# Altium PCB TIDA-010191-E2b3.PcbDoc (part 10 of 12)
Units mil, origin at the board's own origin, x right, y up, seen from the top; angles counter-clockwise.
Board outline 9842.52 x 9842.4 mil, 6 copper layers (Layer 1 - Top Layer, Layer 2 - GND Layer, Layer 3 - Signal, Layer 4 - Signal, Layer 5 - GND, Bottom Layer), stack 59.9 mil thick; 1178 components, 642 nets, 3329 pads, 2967 vias.
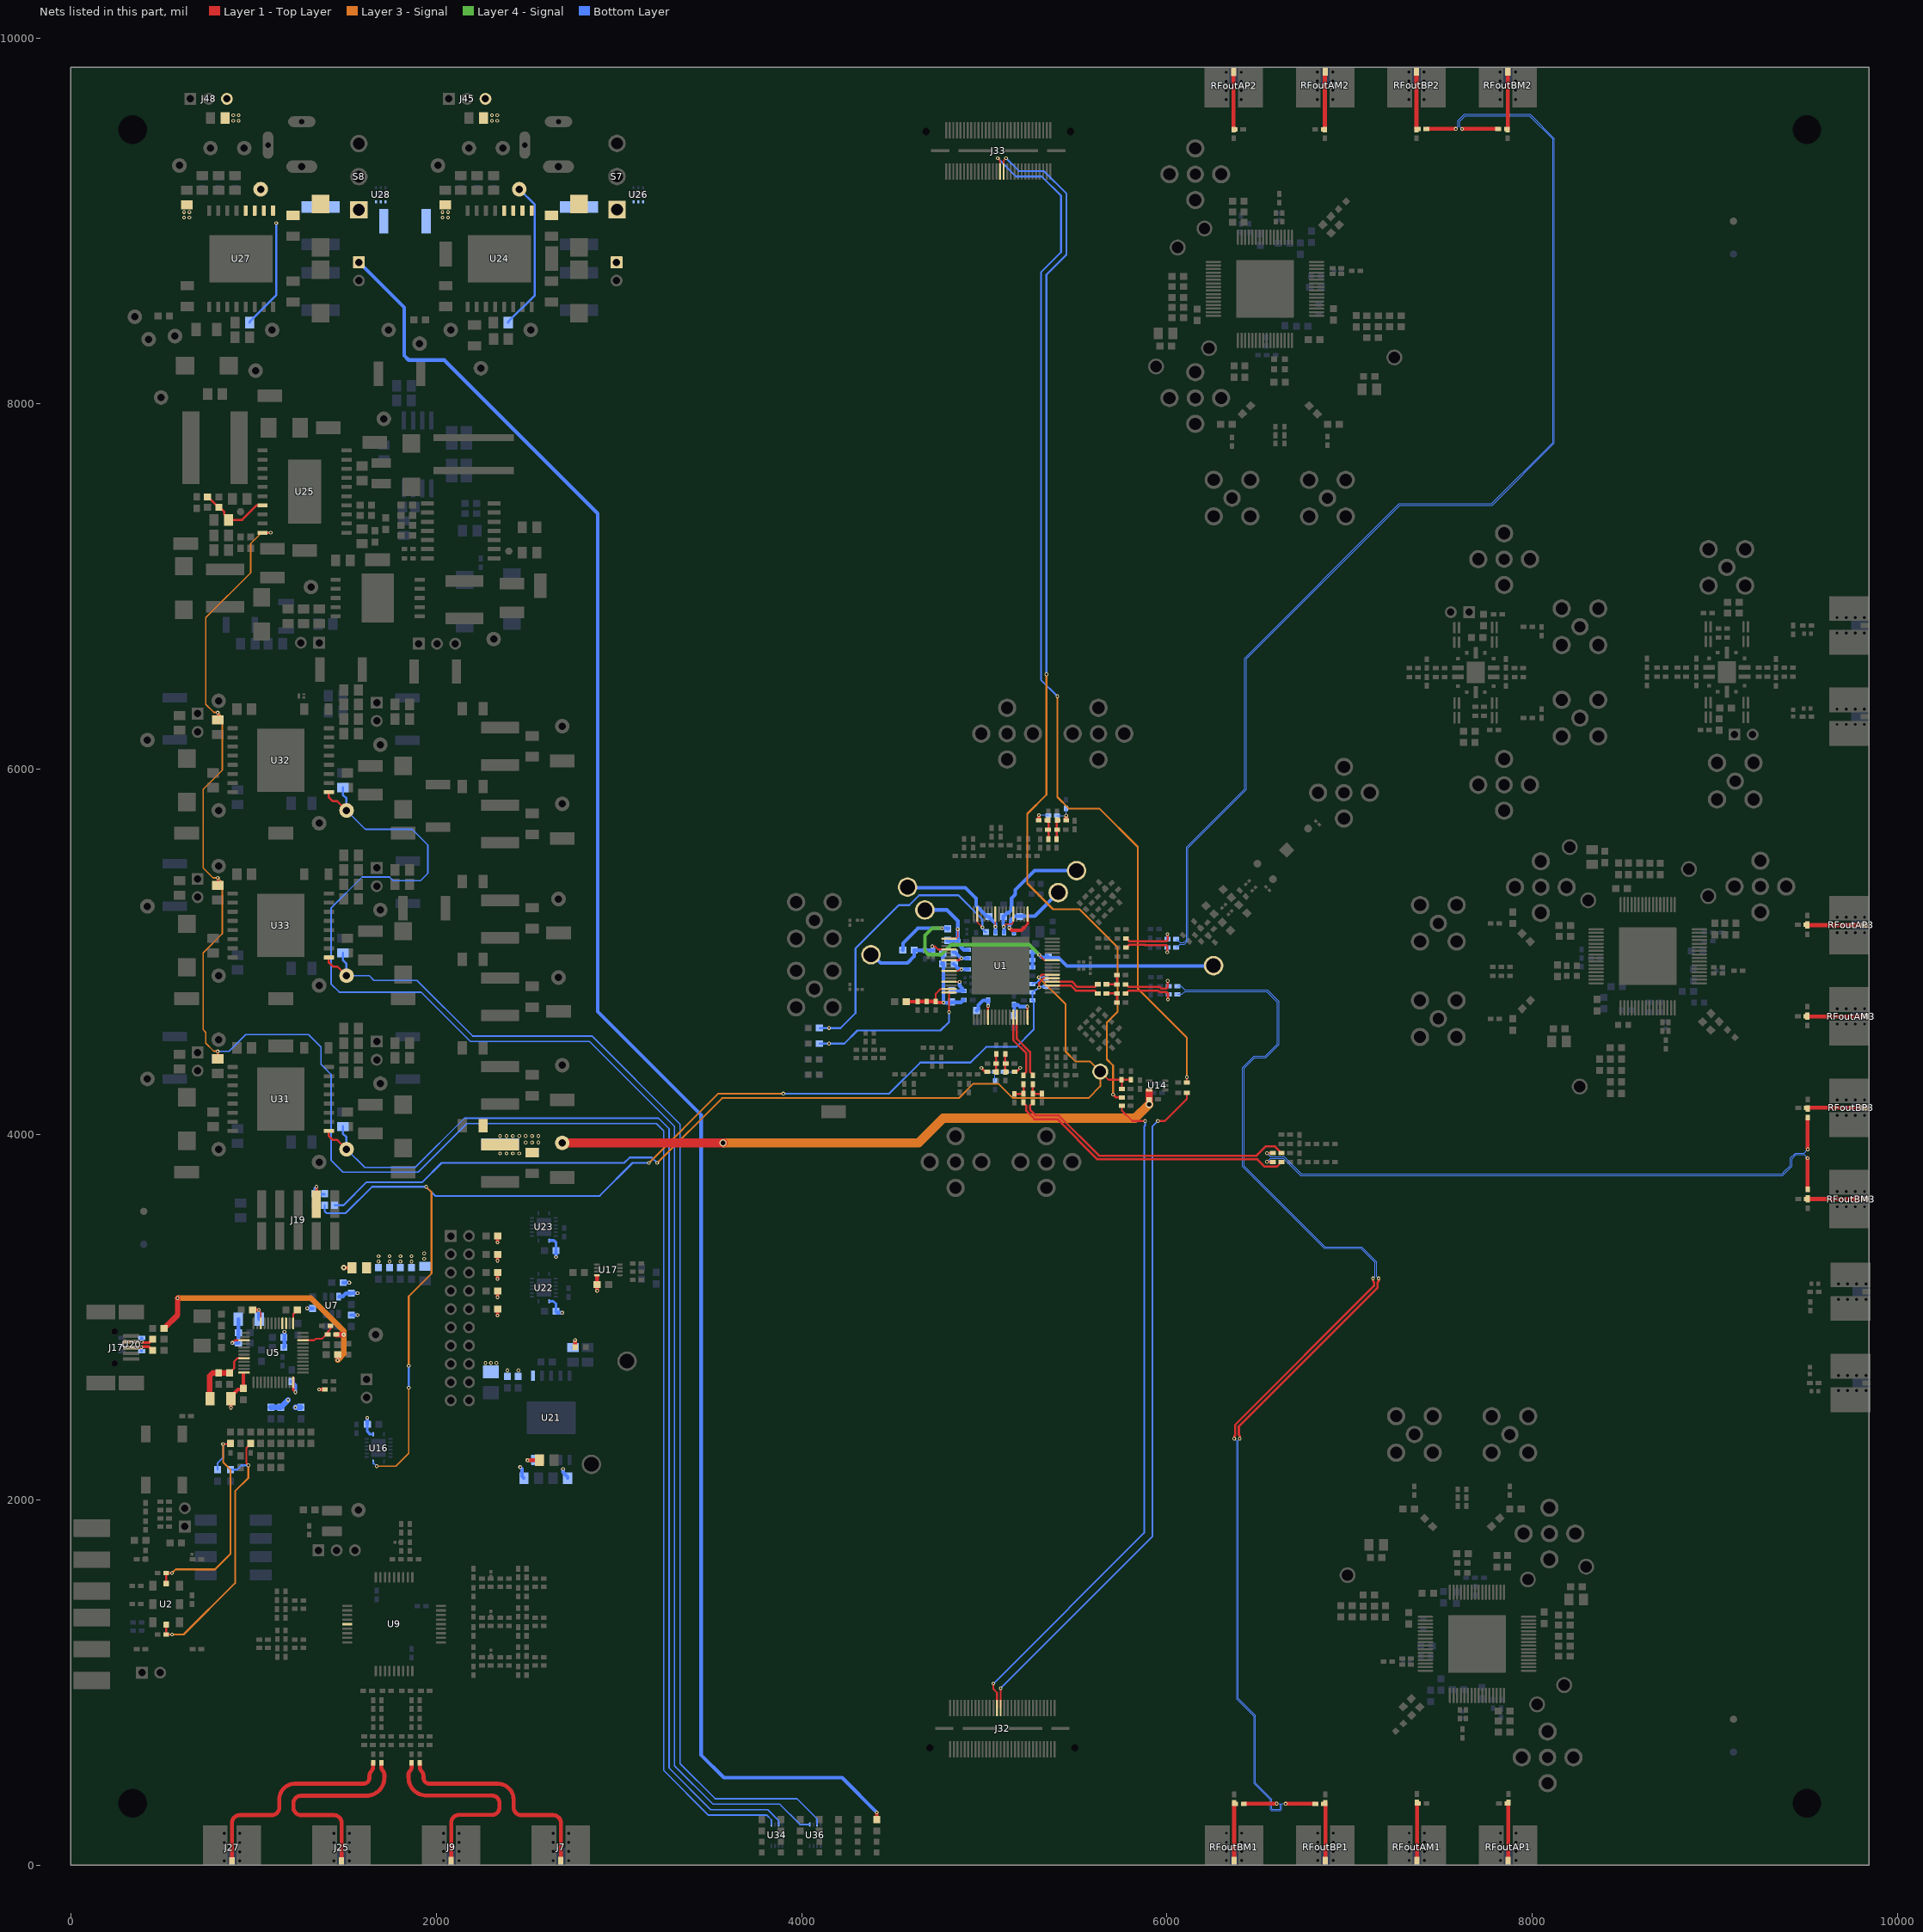
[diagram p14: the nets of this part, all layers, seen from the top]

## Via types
v1: diameter 20, hole 10, Layer 1 - Top Layer to Bottom Layer, tented both sides, 2595 vias
v2: diameter 19.68, hole 7.87, Layer 1 - Top Layer to Bottom Layer, 308 vias
v3: diameter 19.68, hole 7.87, Layer 1 - Top Layer to Bottom Layer, tented both sides, 25 vias
v4: diameter 20, hole 10, Layer 1 - Top Layer to Bottom Layer, 21 vias
v5: diameter 41, hole 25, Layer 1 - Top Layer to Bottom Layer, 10 vias
v6: diameter 24, hole 12, Layer 1 - Top Layer to Bottom Layer, tented both sides, 4 vias
v7: diameter 24, hole 8, Layer 1 - Top Layer to Bottom Layer, tented both sides, 1 vias
v8: diameter 24/24/24/24/24/24 (per signal layer), hole 8, Layer 1 - Top Layer to Bottom Layer, tented both sides, 1 vias
v9: diameter 30, hole 12, Layer 1 - Top Layer to Bottom Layer, tented both sides, 1 vias
v10: diameter 20/20/20/20/20/20 (per signal layer), hole 10, Layer 1 - Top Layer to Bottom Layer, tented both sides, 1 vias

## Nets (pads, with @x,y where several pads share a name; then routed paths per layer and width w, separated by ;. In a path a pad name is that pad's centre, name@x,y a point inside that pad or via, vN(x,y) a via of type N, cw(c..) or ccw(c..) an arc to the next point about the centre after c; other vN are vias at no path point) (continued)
PWRGD: R506.1 R508.1 R519.1 R532.1 U25.20 U34.1 | length 10936.8
  Layer 1 - Top Layer w12: R508.1@805,4415 v1(805,4455.47) ; R532.1@805,5365 v1(805,5405.47) ; R519.1@805,6269.53 v1(805,6310) ; U25.20@1050.08,7295 v1(1095,7295)
  Layer 3 - Signal w8: v1(805,4455.47) 803.47,4457 783,4457 740,4500 740,4560 725,4575 725,4995 830,5100 830,5380.47 v1(805,5405.47) 779.53,5405.47 725,5460 725,5890 830,5995 830,6285 v1(805,6310) 803,6312 783,6312 740,6355 740,6830 985,7075 985,7235 1045,7295 v1(1095,7295)
  Bottom Layer w8: R506.1@805,4415 v1(805,4455.47) 865.8,4455.47 957.47,4547.14 1302.56,4547.14 1370,4479.7 1370,4385 1425,4330 1425,3860 1490,3795 1902.43,3795 2167.43,4060 3205,4060 3245,4020 3245,520 3490,275 3810,275 3835.47,249.53 U34.1@3835.47,224.06
PWRGD_LDO_A: R507.2 TP42.1 U31.9 U34.3 | length 6470.1
  Layer 1 - Top Layer w12: U31.9@1413.5,4020 1413.5,3991.97 1435,3970.47 1459.53,3970.47 TP42.1@1510,3920
  Bottom Layer w8: TP42.1@1510,3920 1610,3820 1885,3820 2155,4090 3217.43,4090 3275,4032.43 3275,532.43 3502.43,305 3815,305 3874.49,245.51 3874.49,224.41 U34.3@3874.84,224.06
  Bottom Layer w12: R507.2@1490,4045.47 R507.2@1490,4045 1490,4005.47 1510,3985.47 TP42.1@1510,3920
PWRGD_LDO_B: R518.2 TP55.1 U32.9 U36.1 | length 8583.5
  Layer 1 - Top Layer w12: U32.9@1413.5,5874.53 1413.5,5846.5 1435,5825 1459.53,5825 TP55.1@1510,5774.53
  Bottom Layer w8: TP55.1@1510,5774.53 1612.95,5671.57 1868.43,5671.57 1955,5585 1955,5430 1915,5390 1765,5390 1745,5410 1595,5410 1425,5240 1425,4825 1470,4780 1917.57,4780 2187.57,4510 2840,4510 3305,4045 3305,544.85 3514.85,335 3880,335 3990.94,224.06 U36.1@4045.47,224.06
  Bottom Layer w12: R518.2@1490,5900 1490,5860 1510,5840 TP55.1@1510,5774.53
PWRGD_LDO_C: R531.2 TP68.1 U33.9 U36.3 | length 6855.9
  Layer 1 - Top Layer w12: U33.9@1413.5,4970 1413.5,4941.97 1435,4920.47 1459.53,4920.47 TP68.1@1510,4870
  Bottom Layer w8: TP68.1@1510,4870 1635,4870 1660,4845 1895,4845 2200,4540 2852.43,4540 3335,4057.43 3335,557.28 3527.28,365 3975,365 4084.84,255.16 U36.3@4084.84,224.06
  Bottom Layer w12: R531.2@1490,4995.47 R531.2@1490,4995 1490,4955.47 1510,4935.47 TP68.1@1510,4870
R_ELMK_SDO: J19.3 R305.2 R311.2 | length 195
  Layer 1 - Top Layer w13.5: J19.3@1345,3620.06 v1(1345,3715)
  Bottom Layer w13.5: v1(1345,3715) 1335,3705 R305.2@1335,3676.5 1335,3674.06 R311.2@1390,3674.06
RESET: C184.1 R35.2 R311.1 R343.1 U1.5 U16.9 | length 6542.5
  Layer 1 - Top Layer w10: v1(5300,4805) 5300,4829.71 5300.13,4829.84 ; 5300.05,4830.05 5326.1,4856.1 U1.5@5372.48,4856.1
  Layer 3 - Signal w8: v1(1675,2185) 1780,2185 1850,2255 v1(1850,2615)
  Layer 3 - Signal w10: v1(1850,2735) 1850,3115 1975,3240 1975,3685 v1(1945,3715) ; v1(3165,3845) 3545,4225 v1(3900,4225)
  Bottom Layer w8: U16.9@1655.47,2210.2 1655.47,2204.53 v1(1675,2185)
  Bottom Layer w10: R311.1@1390,3613.5 1390,3580 1400,3570 1505,3570 1650,3715 v1(1945,3715) 1995,3665 2895,3665 3075,3845 v1(3165,3845) ; v1(1850,2615) v1(1850,2735) ; v1(3900,4225) 4480.33,4225 4650.33,4395 4925,4395 5010,4480 5175,4480 5270,4575 5270,4730 5265,4735 R35.2@5263.62,4735 ; R35.2@5259.68,4735 R35.2@5263.62,4735 ; R343.1@5336.38,4810 5305,4810 v1(5300,4805) 5297.29,4805 5286.23,4793.93 5281.49,4793.93 5267.56,4780 C184.1@5263.62,4780 5263.62,4775 R35.2@5263.62,4735
RFoutA1_N: C48.1 R236.1 RFoutAM1.1 | length 319.8
  Layer 1 - Top Layer w22: RFoutAM1.1@7368.19,23.92 C48.1@7368.19,343.69
RFoutA1_P: C44.1 R234.1 RFoutAP1.1 | length 319.8
  Layer 1 - Top Layer w22: RFoutAP1.1@7868.19,23.92 C44.1@7868.19,343.69
RFoutA2_N: C141.1 R275.1 RFoutAM2.1 | length 319.8
  Layer 1 - Top Layer w22: R275.1@6864.17,9499.29 C141.1@6864.17,9501.06 RFoutAM2.1@6864.17,9819.06
RFoutA2_P: C118.1 R248.1 RFoutAP2.1 | length 318.8
  Layer 1 - Top Layer w22: C118.1@6364.17,9499.29 6364.17,9502.98 RFoutAP2.1@6364.17,9818.05
RFoutA3_N: C158.1 R229.1 R478.1 RFoutAM3.1 | length 319.8
  Layer 1 - Top Layer w22: R229.1@9499.79,4647.38 RFoutAM3.1@9819.56,4647.38
RFoutA3_P: C153.1 R223.1 R266.1 RFoutAP3.1 | length 316.1
  Layer 1 - Top Layer w22: R223.1@9503.48,5147 RFoutAP3.1@9819.56,5147
RFoutB1_N: C57.1 R237.1 RFoutBM1.1 | length 317.3
  Layer 1 - Top Layer w22: RFoutBM1.1@6367.17,23.92 C57.1@6367.17,341.23
RFoutB1_P: C64.1 R241.1 RFoutBP1.1 | length 317.3
  Layer 1 - Top Layer w22: RFoutBP1.1@6867.17,23.92 C64.1@6867.17,341.23
RFoutB2_N: C142.1 R276.1 RFoutBM2.1 | length 317.3
  Layer 1 - Top Layer w22: R276.1@7865.19,9501.75 RFoutBM2.1@7865.19,9819.06
RFoutB2_P: C192.1 R347.1 RFoutBP2.1 | length 317.3
  Layer 1 - Top Layer w22: C192.1@7365.19,9501.75 RFoutBP2.1@7365.19,9819.06
RFoutB3_N: C166.1 R481.1 R482.1 RFoutBM3.1 | length 317.3
  Layer 1 - Top Layer w22: C166.1@9502.25,3647.36 RFoutBM3.1@9819.56,3647.36
RFoutB3_P: C181.1 R483.1 R484.1 RFoutBP3.1 | length 317.3
  Layer 1 - Top Layer w22: C181.1@9502.25,4147.36 9506.13,4147.36 RFoutBP3.1@9819.56,4147.36
SCL: R44.1 R172.1 R178.2 R559.1 U2.8 | length 1265
  Layer 1 - Top Layer w10: U2.8@523.19,1543.07 523.19,1599.57 R44.1@523.62,1600 v1(555,1600) ; v1(833.89,2306.63) 872.53,2306.63 R178.2@875,2309.09
  Layer 3 - Signal w10: v1(555,1600) 575,1620 790,1620 875,1705 875,2166.5 833.89,2207.61 v1(833.89,2306.63)
  Bottom Layer w10: R559.1@804.71,2166.5 804.71,2203.15 833.89,2232.32 v1(833.89,2306.63)
SDA: R43.1 R173.1 R212.2 R560.1 U2.7 | length 1458.7
  Layer 1 - Top Layer w10: R43.1@522.72,1263.12 R43.1@523.19,1263.6 ; U2.7@523.19,1317.48 R43.1@523.19,1263.6 ; v1(554.55,1263.57) R43.1@523.19,1263.6 ; v1(972.27,2190) 961.54,2200.73 961.54,2284.65 980.33,2303.44 R212.2@982.52,2303.44 ; R212.2@985,2308.11 R212.2@985,2309.09
  Layer 3 - Signal w10: v1(554.55,1263.57) 618.57,1263.57 900,1545 900,2048 972.27,2120.27 v1(972.27,2190)
  Bottom Layer w10: R560.1@875,2166.5 910.5,2166.5 934,2190 v1(972.27,2190)
SDCLKOUT1+: R286.2 U1.3 | length 304.2
  Layer 1 - Top Layer w12: U1.3@5336,4816.69 5473.31,4816.69 5501.39,4788.61 5605.15,4788.61 5617.85,4775.91 R286.2@5623.27,4775.91
SDCLKOUT1+*: R25.1 R30.2 R286.1 | length 108.1
  Layer 1 - Top Layer w12: R286.1@5668.22,4773 5726.17,4773 R25.1@5726.27,4773.09 R30.2@5726.27,4723.09
SDCLKOUT1-: R287.2 U1.4 | length 303.9
  Layer 1 - Top Layer w12: U1.4@5336,4836.42 5481.49,4836.42 5509.3,4808.61 5606.15,4808.61 5618.45,4820.91 R287.2@5623.27,4820.91
SDCLKOUT1-*: R27.1 R29.2 R287.1 | length 108.3
  Layer 1 - Top Layer w12: R287.1@5668.22,4823 R27.1@5726.38,4823 5726.38,4872.98 R29.2@5726.27,4873.09
SDCLKout1_LMK_N: R73.1 R237.2 | length 6222.4
  Layer 1 - Top Layer w12: v1(6398.17,2335.71) 6398.17,2350.71 6393.17,2355.71 6393.17,2403.17 7153,3163 7153,3193 7158,3198 v1(7158,3213)
  Layer 1 - Top Layer w22: R237.2@6419.79,337.54 v1(6600,337.54)
  Bottom Layer w3.75: 6484,509.64 6483.92,509.56 6483.92,450.76 6573.18,361.5 6573.18,309.26 6575.38,307.07 6618.05,307.07 6620.24,309.26 6620.24,335.29 6618,337.54 v1(6600,337.54)
  Bottom Layer w4.25: R73.1@6057.13,4812.92 6076.51,4812.92 6096.93,4792.5 6548.7,4792.5 6613,4728.19 6613,4493.58 6540.43,4421.01 6480.01,4421.01 6422.29,4363.29 6422.29,3827.73 6864.02,3386 7064.51,3386 7147,3303.51 7147,3224 v1(7158,3213) ; 6387.67,2324.71 6387.67,916.35 6484,820.02 6484,509.64 ; 6387.67,2325.21 v1(6398.17,2335.71)
SDCLKout1_LMK_P: R72.1 R241.2 | length 6217.2
  Layer 1 - Top Layer w12: v1(6368.17,2335.71) 6368.17,2350.71 6373.17,2355.71 6373.17,2411.45 7133,3171.28 7133,3193 7128,3198 v1(7128,3213)
  Layer 1 - Top Layer w22: v1(6648.49,337.43) R241.2@6812.2,337.54
  Bottom Layer w3.75: 6475.84,506.26 6475.92,506.19 6475.92,447.45 6565.18,358.19 6565.18,305.95 6572.06,299.07 6621.36,299.07 6628.24,305.95 6628.24,335.29 6630.44,337.49 6648.44,337.49 v1(6648.49,337.43)
  Bottom Layer w4.25: R72.1@6057.13,4767.92 6080.92,4767.92 6097,4784 6545.17,4784 6604.5,4724.67 6604.5,4497.1 6536.91,4429.51 6476.49,4429.51 6413.79,4366.81 6413.79,3824.21 6860.5,3377.5 7060.99,3377.5 7138.5,3299.99 7138.5,3223.5 v1(7128,3213) ; v1(6368.17,2335.71) 6379.17,2324.71 6379.17,912.83 6475.84,816.16 6475.84,506.26
SDCLKOUT1_N: R27.2 R73.2 R166.2 | length 310.7
  Layer 1 - Top Layer w12: R27.2@5773.62,4823 5777.56,4823 5783.37,4817.19 5783.37,4815.08 5790.4,4808.05 5960.22,4808.05 5967.73,4800.54 5997.29,4800.54 6004.32,4807.57 6004.32,4841.4 v1(6003.64,4842.08)
  Bottom Layer w3.75: v1(6003.64,4842.08) 6003.64,4819.17 R73.2@6009.89,4812.92
SDCLKOUT1_P: R25.2 R72.2 R203.2 | length 310
  Layer 1 - Top Layer w12: R25.2@5773.51,4773.09 5777.45,4773.09 5783.26,4778.91 5783.26,4781.02 5790.29,4788.05 5951.94,4788.05 5959.45,4780.54 5997.29,4780.54 6005,4772.83 v1(6005,4739)
  Bottom Layer w3.75: v1(6005,4739) 6005,4763.03 R72.2@6009.89,4767.92
SDCLKout3_LMK_N: R92.1 R276.2 | length 6401.9
  Layer 1 - Top Layer w22: v1(7615.02,9505) R276.2@7812.56,9505.44
  Bottom Layer w4.25: R92.1@6050.7,5064.51 R92.1@6055.33,5064.51 ; R92.1@6053.01,5070.26 6071.76,5051.5 6091.5,5051.5 6106.5,5066.5 6106.5,5573.52 6425,5892.02 6425,6608.02 7270.48,7453.5 7776.48,7453.5 8111.5,7788.52 8111.5,9449.5 7984,9577 7632,9577 7601.76,9546.76 7601.76,9518.25 v1(7615.02,9505)
SDCLKout3_LMK_P: R84.1 R347.2 | length 6405.4
  Layer 1 - Top Layer w22: R347.2@7419.5,9505.63 v1(7580.23,9505.63)
  Bottom Layer w4.25: R84.1@6049.59,5025.26 6053.26,5025.26 6071,5043 6095.02,5043 6115,5062.98 6115,5570 6433.5,5888.5 6433.5,6604.5 7274,7445 7780,7445 8120,7785 8120,9453.02 7987.52,9585.5 7628.48,9585.5 7593.26,9550.28 7593.26,9518.22 v1@7580.23,9505.19
SDCLKout3_N: R42.2 R92.2 R208.2 | length 297.1
  Layer 1 - Top Layer w12: R42.2@5775.51,5074.09 5779.45,5074.09 5785.26,5068.28 5785.26,5066.12 5792.29,5059.09 5886.54,5059.09 5887.88,5057.76 5995.31,5057.76 6003.01,5065.46 v1(6003.01,5096.71) ; v1@6003.51,5096.14 v1@6003.64,5096.27
  Bottom Layer w12: R208.2@6002.17,5070.08 R92.2@6002.34,5070.26 6002.59,5070.5 6002.59,5096.29 v1(6003.01,5096.71)
SDCLKout3_P: R41.2 R84.2 R233.2 | length 297
  Layer 1 - Top Layer w12: R41.2@5775.51,5024.09 5779.45,5024.09 5785.26,5029.91 5785.26,5032.06 5792.29,5039.09 5878.26,5039.09 5879.6,5037.76 5995.31,5037.76 6002.34,5030.73 6002.34,4999.47 v1(6001.67,4998.8)
  Bottom Layer w13.5: v1(6001.67,4998.8) 6001.92,4999.05 6001.92,5024.83 R233.2@6002.17,5025.08 R84.2@6002.52,5025.43
SDCLKout5*_N: R10.1 R56.2 R58.2 R293.1 | length 102.7
  Layer 1 - Top Layer w12: R293.1@5351.3,5617.36 R10.1@5351.3,5720.08
SDCLKout5*_P: R2.1 R54.2 R59.2 R292.1 | length 102.7
  Layer 1 - Top Layer w12: R292.1@5396.3,5617.36 5396.3,5670 R2.1@5396.3,5720.08
SDCLKout5_N: R10.2 R204.1 | length 81.8
  Layer 1 - Top Layer w20: R10.2@5298.38,5721 5298.14,5721.24 5298.76,5721.86 v1(5298.76,5749.39)
  Bottom Layer w4.25: v1(5298.76,5749.39) 5346.98,5749.39 R204.1@5350.38,5746
SDCLKout5_P: R2.2 R204.2 R209.1 | length 114.8
  Layer 1 - Top Layer w20: R2.2@5448.62,5721 v1(5448.62,5746)
  Bottom Layer w4.25: R204.2@5397.62,5746 v1(5448.62,5746) ; v1@5448,5746.62 R209.1@5448,5785.38
SDCLKout11_N: R9.2 R143.1 | length 143.8
  Layer 1 - Top Layer w12: R9.2@5164.65,4344 R9.2@5166.62,4344 5175.61,4344 v1(5196.61,4365)
  Bottom Layer w4.25: R143.1@5104.52,4343.12 5176.7,4343.12 v1@5198.58,4365
SDCLKout11_P: R1.2 R141.2 R143.2 | length 173.2
  Layer 1 - Top Layer w12: v1(4984.42,4365) 5005.42,4344 R1.2@5016.38,4344
  Bottom Layer w4.25: v1(4984.42,4365) 5006.3,4343.12 R143.2@5057.28,4343.12 5057.28,4294.43 R141.2@5058.62,4293.09
SDCLKout11a_N: R6.2 R9.1 R11.2 R282.1 | length 97.8
  Layer 1 - Top Layer w12: R6.2@5115,4343.62 5115,4390 R282.1@5115,4441.38
SDCLKout11a_P: R1.1 R3.2 R12.2 R283.1 | length 97.8
  Layer 1 - Top Layer w12: R1.1@5065,4343.62 5065,4390 R283.1@5065,4441.38
SDCLKout13_LMK_N: R136.1 R484.2 | length 3286.7
  Layer 1 - Top Layer w10: v1(6547.57,3898.12) R136.1@6577.26,3898.12
  Layer 1 - Top Layer w22: v1(9506.05,3919.49) R484.2@9506.05,4090.74
  Bottom Layer w4.25: v1(6547.57,3898.12) 6566.74,3878.95 6641.05,3878.95 6735.5,3784.5 9365.5,3784.5 9381.75,3800.75 9411.5,3830.5 9411.5,3872.02 9438.92,3899.44 9486,3899.44 v1(9506.05,3919.49)
SDCLKout13_LMK_P: R135.1 R482.2 | length 3286.8
  Layer 1 - Top Layer w10: v1(6547.57,3851.38) R135.1@6577.76,3851.38
  Layer 1 - Top Layer w22: R482.2@9505.94,3699.98 v1(9505.94,3871)
  Bottom Layer w4.25: v1(6547.57,3851.38) 6566.64,3870.45 6637.53,3870.45 6731.98,3776 9369.02,3776 9371.51,3778.49 9420,3826.98 9420,3868.5 9442.44,3890.94 9486,3890.94 v1(9505.94,3871)
SDCLKOUT13_N: R136.2 R146.1 R357.2 | length 1561
  Layer 1 - Top Layer w12: R357.2@5265.21,4176.69 5265.21,4172.76 5250.21,4157.76 5250.21,4138.08 5283.28,4105 5408.28,4105 5628.1,3885.18 6360.18,3885.18 6360.36,3885 6454.64,3885 6454.82,3885.18 6490.18,3885.18 6540,3935 6591.38,3935 R146.1@6626.38,3900
SDCLKOUT13_P: R8.2 R135.2 R165.1 | length 1585.9
  Layer 1 - Top Layer w12: R8.2@5215.21,4176.69 5215.21,4172.76 5230.21,4157.76 5230.21,4129.79 5275,4085 5400,4085 5619.82,3865.18 6494.82,3865.18 6535,3825 6601.38,3825 R165.1@6626.38,3850
SDCLKout13a_N: R356.2 U1.61 | length 391.2
  Layer 1 - Top Layer w12: U1.61@5178.58,4679 U1.61@5178.58,4642.52 5178.58,4524.32 5250,4452.91 5250,4345 5265,4330 R356.2@5265,4323.62
SDCLKout13a_P: R5.2 U1.60 | length 391.3
  Layer 1 - Top Layer w12: U1.60@5158.85,4679 5158.85,4516.15 5230.27,4444.73 5230.27,4345.27 5215,4330 R5.2@5215,4323.62
SDCLKout13b_N: R13.2 R356.1 R357.1 | length 102.5
  Layer 1 - Top Layer w12: R356.1@5265,4276.38 5265,4224.15 R357.1@5265.21,4223.94 R13.2@5315.21,4223.94
SDCLKout13b_P: R5.1 R8.1 R14.2 | length 102.9
  Layer 1 - Top Layer w12: R14.2@5165,4223.62 5165.32,4223.94 R8.1@5215.21,4223.94 5215,4224.15 R5.1@5215,4276.38
STATUS_LD1: R53.1 R79.1 U1.31 | length 1619.3
  Layer 1 - Top Layer w8: U1.31@4962.05,5207.48 4962.05,5162.95 v1(4990,5135)
  Bottom Layer w10.5: R79.1@4098.39,4583.46 v1(4150,4583.46) 4213.46,4583.46 4295,4665 4295,5020 4531.5,5256.5 4590,5256.5 4643.5,5310 4858.6,5310 4990,5178.6 v1(4990,5135) 4990,5125 5006.03,5108.97 R53.1@5010,5108.94
STATUS_LD2: R80.1 U1.48 | length 918.3
  Layer 1 - Top Layer w10: v1(4807.52,4670) U1.48@4807.52,4777.36
  Bottom Layer w10: v1(4150,4498.46) 4234.46,4498.46 4306,4570 4760,4570 4807.52,4617.52 v1(4807.52,4670)
  Bottom Layer w10.5: R80.1@4098.39,4498.46 v1(4150,4498.46)
SYNC: C185.1 R190.1 R200.2 R201.2 R202.2 R306.1 SYNC.1 U1.6 | length 5751.6
  Layer 1 - Top Layer w10: v1(5298.14,4861.2) 5301.06,4861.2 5315.64,4875.79 U1.6@5372.48,4875.79 ; SYNC.1@5635,4345 5679.53,4300.47 R202.2@5751.89,4300.47 ; R201.2@5753.27,4249.09 5753.27,4299.09 R202.2@5751.89,4300.47 ; R200.2@5801.89,4300.47 R202.2@5751.89,4300.47
  Layer 3 - Signal w10: v1(3210,3845) 3565,4200 4861,4200 4940,4279 5077,4279 5156,4200 5570,4200 5635,4265 SYNC.1@5635,4345 5579.73,4400.27 5499.73,4400.27 5445,4455 5445,4714.34 v1(5298.14,4861.2)
  Bottom Layer w10: R306.1@1445,3613.5 1493.5,3613.5 1620,3740 1925,3740 2030,3845 3030,3845 3060,3875 3180,3875 v1(3210,3845) ; C185.1@5263.62,4825 5270.43,4831.81 5286.81,4831.81 5298.09,4843.09 5298.09,4861.15 v1(5298.14,4861.2) 5300.84,4861.2 5301.16,4861.52 5325.92,4861.52 5332.44,4855 R190.1@5336.38,4855
SYNC1_IN: J32.31 R192.1 | length 3812.5
  Layer 1 - Top Layer w10: J32.31@5089.28,862.12 5089.28,909.8 5090,910.52 v1(5090,970) ; v1(5950,4075) 5988.25,4075 6108.62,4195.37 R192.1@6108.62,4230
  Bottom Layer w10: v1(5090,970) 5920.96,1800.96 5920.96,4000.96 5920.96,4045.96 v1(5950,4075)
SYNC1_OUT: J32.33 R196.1 | length 3742.7
  Layer 1 - Top Layer w10: v1(5050,995) 5050,965 5069.6,945.4 J32.33@5069.6,862.12 ; R196.1@5753.27,4159.09 5753.27,4131.73 5810,4075 v1(5880.19,4075)
  Bottom Layer w10: v1(5050,995) 5875,1820 5875,4045 5880,4050 5880,4074.81 v1(5880.19,4075)
SYNC2_IN: J33.31 R194.1 | length 5838.1
  Layer 1 - Top Layer w8: v1(5073.82,9345) 5086.46,9332.36 J33.31@5086.46,9272.88
  Layer 1 - Top Layer w10: R194.1@6108.62,4285 v1(6108.62,4315)
  Layer 3 - Signal w10.5: v1(5400,6400) 5400,5847.62 5462.62,5785 5630,5785 5840.08,5574.92 5840.08,4799.92 6108.28,4531.72 v1@6108.28,4314.66
  Bottom Layer w10: v1(5073.82,9345) 5173.82,9245 5315,9245 5420,9140 5420,8830 5310,8720 5310,6490 v1(5400,6400)
SYNC2_OUT: J33.33 R197.2 | length 5891.7
  Layer 1 - Top Layer w8: J33.33@5106.14,9272.88 5106.14,9332.36 v1(5118.78,9345)
  Layer 1 - Top Layer w13.5: v1(5705,4220) 5720.91,4204.09 R197.2@5753.27,4204.09
  Layer 3 - Signal w10.5: v1(5340,6520) 5340,5861.38 5235,5756.38 5235,5375.48 5376.47,5234 5521,5234 5649.6,5105.4 5649.6,5105 ; 5650,5105 5730,5025 5730,4672.65 5670.51,4613.16 5670.51,4412.49 5705,4378 v1(5705,4220)
  Bottom Layer w10: v1(5118.78,9345) 5188.78,9275 5325,9275 5450,9150 5450,8817.57 5340,8707.57 v1(5340,6520)
USB_N: J17.2 R149.1 U20.4 | length 149.2
  Layer 1 - Top Layer w15: J17.2@331.65,2866.5 v1(388.5,2866.5) 394,2861 428.52,2861 447.52,2880 R149.1@448.5,2880
  Bottom Layer w7: U20.4@388.5,2887.77 U20.4@389.13,2888.4
  Bottom Layer w15: v1(388.5,2866.5) U20.4@388.5,2887.77
USB_P: J17.3 R150.1 U20.5 | length 148.2
  Layer 1 - Top Layer w15: J17.3@331.65,2835 v1(388,2835) 392,2839 428.52,2839 447.52,2820 R150.1@448.5,2820
  Bottom Layer w7: U20.5@388,2814.73 U20.5@389.13,2813.6
  Bottom Layer w15: U20.5@388,2814.73 v1(388,2835)
USB_RESET: R155.1 R174.2 U5.34 | length 194.4
  Layer 1 - Top Layer w10: U5.34@1271.42,2874.49 1271.76,2874.83 1332.87,2874.83 1340,2881.97 1374.88,2881.97 R155.1@1398.5,2905.59 ; R155.1@1406.38,2905.59 1406.38,2920.4 1422.13,2936.15 R174.2@1422.13,2953.5
VBB: U9.5
VBUS: R147.2 R155.2 R383.2 | length 1426.7
  Layer 1 - Top Layer w20: v1(1461.5,2765) R147.2@1461.5,2795.59
  Layer 1 - Top Layer w30: R383.2@511.5,2940 512.48,2940 585,3012.52 v1(585,3105) ; R155.2@1453.62,2905.59 1472.37,2905.59 1472.96,2905 v8(1495,2905)
  Layer 3 - Signal w30: v1(585,3105) 1315,3105 1495,2925 v8(1495,2905) 1495,2798.5 v1(1461.5,2765)
VCC1_VCO: C23.1 C24.1 C25.1 L2.1 L30.2 L31.2 TP1.1 U1.10 | length 2411.8
  Layer 1 - Top Layer w10: v1(5300.48,4983.87) 5300.48,4982.97 5328.92,4954.53 U1.10@5372.48,4954.53
  Layer 4 - Signal w20: v1(4770,5130) 4715.34,5130 4675,5089.66 4675,5005 4695,4985 4765,4985 4820,5040 5244.34,5040 v1(5300.48,4983.87)
  Bottom Layer w20: L31.2@4553.5,5010 4555,5011.5 4555,5048.07 4636.93,5130 v1(4770,5130) 4803.5,5130 L30.2@4800,5126.5 ; C23.1@5263.62,4915 C24.1@5263.62,4955 C25.1@5263.62,5000 5284.34,5000 v1(5300.48,4983.87) 5314.47,4969.87 5342.23,4969.87 5342.23,4981.37 5350.93,4972.67 L2.1@5350.93,4971.68 5354.54,4968.06 5407.1,4968.06 5451.54,4923.62 TP1.1@6255,4923.62
VCC2_CG1: C27.1 L4.1 TP2.1 U1.17 | length 579.9
  Layer 1 - Top Layer w12: 5217.95,5133.3 5237.64,5152.98 U1.17@5237.64,5207.48
  Layer 1 - Top Layer w20: v1(5136.5,5131.81) 5149.84,5118.48 5203.13,5118.48 5217.95,5133.3
  Bottom Layer w20: v1@5136.6,5134.47 5137.83,5135.69 5137.83,5146.45 5145.07,5153.7 5145.07,5174.79 5166.74,5196.46 5276.46,5196.46 TP2.1@5405,5325 ; v1@5136.81,5131.51 5139.45,5131.51 5162.02,5108.94 C27.1@5162.02,5105
VCC3_SYSREF: C32.1 L7.1 TP3.1 U1.21 | length 756.5
  Layer 1 - Top Layer w8: v1(5105.47,5138.15) 5120.37,5153.05 5148.74,5153.05 5158.9,5163.21 U1.21@5158.9,5207.48
  Bottom Layer w20: v1@5105.67,5145.29 5103.2,5147.76 5103.2,5191.7 L7.1@5105,5193.5 5105,5194.49 5124.1,5213.59 5133.03,5213.59 5148.95,5229.51 5148.95,5291.17 ; v1@5106.08,5143.35 5108.12,5141.31 5108.12,5105.4 C32.1@5108.52,5105 C32.1@5108.52,5108.94 ; 5148.62,5293.29 5170,5314.67 5170,5340 5275,5445 TP3.1@5505,5445
VCC4_CG2: C33.1 L8.1 TP4.1 U1.26 | length 707.9
  Layer 1 - Top Layer w8: v1(5060.48,5138.14) U1.26@5060.48,5207.48
  Bottom Layer w20: TP4.1@4580,5355 4583.15,5351.85 4896.45,5351.85 4955,5293.3 4955,5253.58 5015.07,5193.5 L8.1@5025,5193.5 5025,5192.52 5061.06,5156.46 C33.1@5061.06,5105
Vcc5_DIG: C10.1 C355.1 L30.1 TP84.1 U1.33 | length 556.8
  Layer 1 - Top Layer w8: U1.33@4807.52,5072.64 4808.25,5073.37 4845.37,5073.37 4855,5083 v1(4855,5124.72)
  Bottom Layer w20: TP84.1@4675,5230 4795,5230 4855,5170 v1(4855,5124.72) 4855,5060.59 C355.1@4854.41,5060 ; L30.1@4796.5,5063.5 L30.1@4799.02,5063.5 ; L30.1@4800,5063.5 L30.1@4799.02,5063.5 ; C10.1@4911.38,5011.5 4888.5,5011.5 4858.35,5041.65 4858.35,5060 C355.1@4854.41,5060 ; L30.1@4799.02,5063.5 4802.52,5060 C355.1@4854.41,5060
Vcc6_PLL1: C11.1 C356.1 L31.1 TP83.1 U1.36 | length 527.9
  Layer 1 - Top Layer w10: v1@4717.71,5030 4730,5030 4746.42,5013.58 U1.36@4807.52,5013.58
  Bottom Layer w20: TP83.1@4380,4985 4387.59,4985 4432.59,4940 4580,4940 4616.5,4976.5 L31.1@4616.5,5010 4617.87,5008.62 C356.1@4675,5008.62 C11.1@4720,5008.62 4718.19,5010.43 4718.19,5026.81 v1(4715,5030)
VCC7_OSCOUT: C1.1 L1.1 U1.39 | length 155.9
  Layer 1 - Top Layer w12: U1.39@4807.52,4954.53 4807.61,4954.62 4860.7,4954.62 4868.61,4962.53 v1@4871.54,4962.53
  Bottom Layer w20: L1.1@4831.5,5000 L1.1@4832.48,5000 ; L1.1@4836.5,5000 4837.48,5000 4870,4967.48 v1@4870,4965 ; v1(4875,4965) 4910.75,4965 C1.1@4911.38,4964.37 C1.1@4910.31,4963.3
VCC8_OSCIN: C26.2 L3.1 U1.42 | length 161.3
  Layer 1 - Top Layer w8: U1.42@4807.52,4895.47 4808.25,4896.2 4858.94,4896.2 4867.74,4905 v1(4875,4905)
  Bottom Layer w20: L3.1@4831.5,4935 4832.48,4935 4862.48,4905 v1@4870,4905 ; v1(4875,4905) C26.2@4909.57,4905 ; C26.2@4911.38,4905 C26.2@4909.57,4905 ; C26.2@4911.38,4906.81 C26.2@4909.57,4905
VCC9_CP2: C31.2 L6.1 U1.45 | length 184.3
  Layer 1 - Top Layer w10: U1.45@4807.52,4836.42 4807.61,4836.33 4864.38,4836.33 v1(4864.48,4836.23)
  Bottom Layer w20: L6.1@4820.74,4789 4823.24,4786.5 C31.2@4884.88,4786.5 ; v1(4864.48,4836.23) 4864.48,4815.82 4878.32,4801.98 4878.32,4793.06 4883.07,4788.31 C31.2@4884.88,4786.5 ; C31.2@4888.82,4786.5 C31.2@4884.88,4786.5
VCC10_PLL2: C28.1 C29.1 C30.1 C85.2 L1.2 L3.2 L5.1 L6.2 U1.47 | length 736.6
  Layer 1 - Top Layer w10: C30.1@4735,4728.62 4735,4772 4759.7,4796.7 4807.17,4796.7 U1.47@4807.52,4797.05
  Layer 1 - Top Layer w20: L5.1@4572.1,4727.52 4633.9,4727.52 C28.1@4635,4728.62 C29.1@4685,4728.62 C30.1@4735,4728.62 4735,4725.31 4736.81,4723.5 v1(4776.5,4723.5)
  Bottom Layer w20: L3.2@4768.5,4935 4767.52,4935 L3.2@4770,4932.52 ; L1.2@4773.5,5000 L1.2@4773.5,4994 L3.2@4773.5,4935 4776.5,4932.01 v1(4776.5,4723.5) ; v1@4777.24,4722.32 4817.06,4722.32 L6.2@4820.74,4726 4822.81,4723.94 4872.5,4723.94 4884.94,4736.38 C85.2@4888.88,4736.38
VCC11_CG3: C34.1 L9.1 U1.53 | length 191.4
  Layer 1 - Top Layer w12: U1.53@5021.1,4642.52 v1(5021.1,4705)
  Bottom Layer w20: L9.1@4958.62,4680 4967.32,4688.7 4967.32,4708.72 4993.6,4735 5020.62,4735 C34.1@5021.1,4735.48 ; v1(5021.1,4705) C34.1@5021.1,4735.48 ; C34.1@5022,4736.38 C34.1@5021.1,4735.48
VCC12_CG0: C35.1 L10.1 U1.64 | length 196.6
  Layer 1 - Top Layer w12: v1(5235.4,4700.86) 5235.4,4698.7 5237.54,4696.56 5237.54,4642.61 U1.64@5237.64,4642.52
  Bottom Layer w20: C35.1@5163.5,4712.76 C35.1@5163.5,4711.52 ; L10.1@5165,4651.5 5165,4707.32 5163.5,4708.82 C35.1@5163.5,4711.52 ; v1@5234.48,4700.6 5233.82,4701.26 5193.43,4701.26 5184.98,4709.71 5165.31,4709.71 C35.1@5163.5,4711.52
VCCA: C115.2 U5.37 | length 83.2
  Layer 1 - Top Layer w10: U5.37@1218.27,2967.01 1218.27,3016.77 1226.81,3025.31 1226.81,3026.3 1240.51,3040 C115.2@1241.5,3040
VDDD33: C2.1 C280.2 C281.2 C282.1 C283.1 C327.1 C328.1 C329.1 C335.1 C337.1 L25.2 NT1.1 TP46.1 U14.5 | length 3367
  Layer 1 - Top Layer w40: v5(5902.6,4165) U14.5@5902.6,4240
  Layer 1 - Top Layer w50: TP46.1@2690,3955 v5(3570,3955)
  Layer 3 - Signal w50: v5@3575,3955 4640,3955 4775,4090 5825,4090 v5@5900,4165
  other v1: 1685,3305 1745,3305 1805,3305 1865,3305 1935,3320 1685,3335 1745,3335 1805,3335 1865,3335 1935,3350 2350,3897.24 2385,3897.24 2420,3897.24 2455,3897.24 2490,3957.24 2525,3957.24 2560,3957.24 2350,3992.24 2385,3992.24 2420,3992.24 2455,3992.24 2490,3992.24 2525,3992.24 2560,3992.24
VIN_P5V0: C223.2 C227.1 C228.2 C234.1 J43.1 J45.3 R408.2 R410.2 R422.1 S7.1 TP11.1 U24.1 U24.2 U24.3 U24.4 U26.4 U26.5 U26.6 | length 825.3
  Bottom Layer w12: C223.2@2395,8445 2395,8450 2540,8595 2540,9090 TP11.1@2455,9175
  other v1: 2035,9020 2065,9020 2035,9050 2065,9050 2305,9550 2335,9550 2305,9580 2335,9580
VIN_P5V0_Redundant: C249.2 C255.1 C256.2 C257.1 J46.1 J48.3 R422.2 R424.2 R425.2 R544.2 S8.1 TP27.1 U27.1 U27.2 U27.3 U27.4 U28.4 U28.5 U28.6 | length 10796.1
  Layer 1 - Top Layer w20: R544.2@4412.19,251.5 v1(4412.19,290)
  Bottom Layer w12: C249.2@980,8445 980,8450 1125,8595 v1(1125,8990)
  Bottom Layer w20: J46.1@1577.56,8775 1825,8527.56 1825,8265.02 1850.02,8240 2045,8240 2885,7400 2885,6365 2885,4673.14 3450,4108.14 3450,604.91 3574.91,480 4222.19,480 v1(4412.19,290)
  other v1: 620,9020 650,9020 620,9050 650,9050 890,9550 920,9550 890,9580 920,9580
VPHY: C107.1 C111.1 L15.2 U5.3 | length 233.3
  Layer 1 - Top Layer w10: v1(885,2860) 899.49,2874.49 U5.3@948.58,2874.49
  Bottom Layer w20: v1(885,2860) C111.1@918.5,2860 C107.1@918.5,2915 918.5,2989.41 L15.2@917.91,2990
VPLL: C112.1 C114.1 L16.2 U5.8 | length 374.8
  Layer 1 - Top Layer w11: C114.1@870,2697.09 895,2722.09 895,2758 912.91,2775.91 948.43,2775.91 U5.8@948.58,2776.06
  Layer 1 - Top Layer w30: L16.2@762.91,2555.59 760,2558.5 760,2680 776.5,2696.5 C112.1@810,2696.5 C114.1@870,2696.5
VREGIN: C106.1 C108.1 C109.1 C110.1 C117.1 C124.2 C196.1 C199.1 C218.1 C219.1 C220.1 C221.1 C222.1 D7.1 L15.1 L16.1 NT1.2 R151.2 R152.2 R160.2 R161.2 R162.2 R205.2 R308.1 R309.1 R310.1 R312.1 R370.2 R386.2 R387.2 R405.1 R557.2 R558.2 U5.12 U5.24 U5.39 U5.40 U5.46 U7.6 U16.16 U17.8 U21.1 U21.10 U22.16 U23.16 | length 1966.7
  Layer 1 - Top Layer w8: v1(1030,3040) 1041.1,3028.9 U5.46@1041.1,2967.01
  Layer 1 - Top Layer w12: U5.24@1218.27,2671 U5.24@1218.27,2644.17 1218.27,2601.73 v1(1230,2590)
  Layer 1 - Top Layer w20: v1(877.09,2505) L16.1@877.09,2555.59 877.09,2566.42 915.67,2605 938.5,2605 C108.1@945,2611.5 U5.12@945,2693 ; C110.1@996.5,3040 v1(1030,3040) ; v1(1360,2605) R370.2@1391.38,2605 ; v9(1495,3271.5) 1538.5,3271.5 NT1.2@1539,3271 ; v1(2336.5,3010) R405.1@2336.5,3045 ; v1(2336.5,3110) R312.1@2336.5,3145 ; v1(2336.5,3210) R310.1@2336.5,3245 ; v1(2336.5,3310) R309.1@2336.5,3345 ; v1(2336.5,3410) R308.1@2336.5,3445 ; v1(2500,2217.44) R386.2@2565,2217.44 ; D7.1@2760.47,2837.44 v1(2760.47,2875) ; U17.8@2880.68,3226 2880.68,3180.75 C199.1@2881.43,3180 v1(2881.43,3145)
  Bottom Layer w15: C196.1@1623.5,2415 1623.5,2375 1638.7,2359.8 U16.16@1652,2359.8 ; U22.16@2623,3087.76 2642.24,3087.76 2656.5,3073.5 C221.1@2656.5,3032.56 ; U23.16@2623,3420.2 2644.67,3420.2 2656.5,3408.37 C222.1@2656.5,3365
  Bottom Layer w20: v1(1030,3040) 1030,2992.09 L15.1@1032.09,2990 ; C106.1@1166.5,2835 1170,2838.5 v1(1170,2920) ; C109.1@1210,2649.09 1230,2629.09 v1(1230,2590) ; v1(1295,3049.09) R162.2@1325,3049.09 ; U7.6@1467.4,3112.83 1469.57,3115 1490,3115 1506.1,3131.1 1535,3131.1 C124.2@1535,3132.09 v1(1570,3132.09) ; R161.2@1491.5,3190 v1(1525,3190) ; R160.2@1535,3012.58 v1(1570,3012.58) ; C196.1@1623.5,2415 v1(1623.5,2450) ; v1(2460,2180) 2470.54,2169.46 2470.54,2129.46 R557.2@2480,2120 ; v1(2500,2217.44) 2529.17,2217.44 2530,2218.27 U21.10@2530,2220.08 ; C221.1@2656.5,3032.56 2664.06,3025 v1(2690,3025) ; v1(2656.5,3330) C222.1@2656.5,3365 ; v1(2695,2170) 2694.78,2169.78 2694.78,2151.72 2720,2126.5 R558.2@2720,2120 ; R387.2@2750,2835 2760.47,2845.47 v1(2760.47,2875)
  Bottom Layer w30: R151.2@1095,2507.09 R152.2@1150,2507.09 1150,2508.07 v1(1190,2548.07) ; v1(1230,2507.09) R205.2@1260,2507.09
  other v1: 2390,2710 2450,2710 2270,2750 2300,2750 2330,2750
VSENSE: C229.2 R413.1 R415.2 U25.17 | length 394.2
  Layer 1 - Top Layer w12: R415.2@748.5,7490 753,7490 808,7435 R413.1@811.5,7435 815,7435 840,7410 840,7396.5 865,7371.5 C229.2@865,7365 935,7365 ; 939,7365 1019,7445 U25.17@1050.08,7445
Y4A_SMA: J9.1 R433.2 | length 1210.3
  Layer 1 - Top Layer w22: R433.2@1866,561.38 1866,539.14 cw(c1831.86,539.14) 1856,515 ccw(c1872.9,498.1) 1849,498.1 1849,481 ; J9.1@2083,23.5 2083,234 cw(c2125,234) 2125,276 2305,276 ; 2306,276 2305,276 ; 1849.01,480 ccw(c1947.87,481) 1947.87,382.13 2306,382.13 cw(c2306,341.13) 2347,341.13 2347,318 cw(c2305,318) 2305,276 ; 1849.01,480 cw(c1947.87,481) 1849,481 ; 1849,480 1849,481
Y4B_SMA: J7.1 R431.2 | length 1207.7
  Layer 1 - Top Layer w22: R431.2@1911,561.38 1911,539.14 ccw(c1945.14,539.14) 1921,515 ; 1921,515 cw(c1896.86,490.86) 1931,490.86 1931,480 ccw(c1964,480) 1964,447 2337,447 cw(c2337,360) 2424,360 2424,317 ccw(c2466,317) 2466,275 2641,275 cw(c2641,233) 2683,233 J7.1@2683,23.5
Y5A_SMA: J27.1 R400.2 | length 1209.5
  Layer 1 - Top Layer w22: J27.1@883,22.5 883,233 cw(c925,233) 925,275 1100,275 ccw(c1100,317) 1142,317 1142,361.9 ; 1142,361.9 cw(c1227.1,361.9) 1227.1,447 1602,447 ccw(c1602,480) 1635,480 1635,490.86 cw(c1669.14,490.86) 1645,515 ; 1645,515 ccw(c1620.86,539.14) 1655,539.14 R400.2@1655,561.38
Y5B_SMA: J25.1 R398.2 | length 1210.3
  Layer 1 - Top Layer w22: 1260,275 1261,275 ; J25.1@1483,22.5 1483,233 ccw(c1441,233) 1441,275 1261,275 ; R398.2@1700,561.38 1700,539.14 ccw(c1734.14,539.14) 1710,515 cw(c1693.1,498.1) 1717,498.1 1717,480 cw(c1618.13,480) 1618.13,381.13 1260,381.13 ccw(c1260,340.13) 1219,340.13 1219,317 ccw(c1261,317) 1261,275
pads on no net: FID1.1 FID2.1 FID3.1 FID4.1 FID5.1 FID6.1 J17. J17.4 J19.5 J20.11 J20.12 J20.13 J20.14 J20.15 J20.16 J20.17 J20.18 J20.19 J20.20 J32.1 J32.4 J32.6 J32.12 J32.14 J32.20 J32.22 J32.28 J32.30 J32.36 J32.38 J32.44 J32.46 J32.52 J32.54 J32.MH1 J32.MH2 J33.1 J33.4 J33.6 J33.12 J33.14 J33.20 J33.22 J33.28 J33.30 J33.36 J33.38 J33.44 J33.46 J33.52 J33.54 J33.MH1 J33.MH2 LBL1.0 S1.1 S2.1 S3.1 S4.1 S7.3 S8.3 SH-J1.0 SH-J2.0 SH-J3.0 SH-J4.0 SH-J30.0 U2.1 U2.2@596.03,1414.52 U2.2@596.03,1446.02 U2.3@596.03,1514.52 U2.3@596.03,1546.02 U2.4@450.36,1514.52 U2.4@450.36,1546.02 U2.5@450.36,1414.52 U2.5@450.36,1446.02 U2.6@450.36,1314.52 U2.6@450.36,1346.02 U5.26 U5.27 U5.28 U5.29 U5.30 U5.33 U9.11 U9.12 U9.19 U9.20 U9.31 U9.32 U9.33 U9.34 U20.1 U20.3 U21.11@2516.81,2382.09 U21.11@2516.81,2427.36 U21.11@2516.81,2472.64 U21.11@2516.81,2517.91 U21.11@2562.09,2382.09 U21.11@2562.09,2427.36 U21.11@2562.09,2472.64 U21.11@2562.09,2517.91 U21.11@2607.36,2382.09 U21.11@2607.36,2427.36 U21.11@2607.36,2472.64 U21.11@2607.36,2517.91 U21.11@2652.64,2382.09 U21.11@2652.64,2427.36 U21.11@2652.64,2472.64 U21.11@2652.64,2517.91 U21.11@2697.91,2382.09 U21.11@2697.91,2427.36 U21.11@2697.91,2472.64 U21.11@2697.91,2517.91 U21.11@2743.19,2382.09 U21.11@2743.19,2427.36 U21.11@2743.19,2472.64 U21.11@2743.19,2517.91 U23.12 U23.13 U23.14 U26.7@3089.84,9145 U26.7@3125.28,9145 U28.7@1679.84,9145 U28.7@1715.28,9145 U29.7 U35.11@1612.09,6824.37 U35.11@1612.09,6869.65 U35.11@1612.09,6914.92 U35.11@1612.09,6960.2 U35.11@1612.09,7005.47 U35.11@1612.09,7050.75 U35.11@1657.36,6824.37 U35.11@1657.36,6869.65 U35.11@1657.36,6914.92 U35.11@1657.36,6960.2 U35.11@1657.36,7005.47 U35.11@1657.36,7050.75 U35.11@1702.64,6824.37 U35.11@1702.64,6869.65 U35.11@1702.64,6914.92 U35.11@1702.64,6960.2 U35.11@1702.64,7005.47 U35.11@1702.64,7050.75 U35.11@1747.91,6824.37 U35.11@1747.91,6869.65 U35.11@1747.91,6914.92 U35.11@1747.91,6960.2 U35.11@1747.91,7005.47 U35.11@1747.91,7050.75

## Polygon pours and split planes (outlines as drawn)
VIN_P5V0_Redundant on Bottom Layer "Bottom Layer-VIN_P5V0_Redundant" (solid, remove dead copper, pour order 2): 485,9055 515,9085 950,9085 980,9115 980,9200 1130,9350 1130,9485 1100,9515 840,9515 820,9535 820,9705 840,9725 1440,9725 1515,9650 1515,9200 1555,9160 1605,9160 1650,9115 1745,9115 1785,9075 1785,9015 1785,8960 1755,8930 1495,8930 1450,8975 1170,8975 1125,8930 515,8930 485,8960
VIN_P5V0 on Bottom Layer "Bottom Layer-VIN_P5V0" (solid, remove dead copper, pour order 0): 1890,9055 1920,9085 2355,9085 2385,9115 2385,9200 2535,9350 2535,9485 2505,9515 2245,9515 2225,9535 2225,9705 2245,9725 2845,9725 2920,9650 2920,9200 2960,9160 3010,9160 3055,9115 3150,9115 3190,9075 3190,9015 3150,8975 2585,8975 2540,8930 1920,8930 1890,8960
VDDD33 on Layer 1 - Top Layer "VDDD33_L01_P043" (solid, remove dead copper, pour order 43): 1619,3325.5 1664.5,3371 1924,3371 1956,3371 1956,3316 1880.09,3240.09 1619,3240.09
GND on Layer 1 - Top Layer "Layer 1 - Top Layer-GND" (solid, remove dead copper, pour order 40): 8549.29,4511.44 8547.92,4512.82 8547.92,7304 9819.29,7304 9819.29,2446 8549.29,2446
GND on Layer 1 - Top Layer "Layer 1 - Top Layer-GND" (solid, remove dead copper, pour order 18): 8107.35,9822.98 8107.35,8552.98 6997.35,8552.98 6857.35,8692.98 6577.35,8692.98 6577.35,8937.98 6482.35,9032.98 6482.35,9112.98 6397.35,9197.98 6267.35,9197.98 6237.35,9227.98 6237.35,9317.98 6217.35,9337.98 6117.35,9337.98 6097.35,9357.98 6097.35,9822.98 6107.35,9822.98
GND on Layer 1 - Top Layer "Layer 1 - Top Layer-GND" (solid, remove dead copper, pour order 16): 6127.83,20 6127.83,1152.52 6265.31,1290 7240.35,1290 7377.83,1152.52 7657.83,1152.52 7657.83,907.52 7752.83,812.52 7752.83,732.52 7837.83,647.52 7967.83,647.52 7997.83,617.52 7997.83,527.52 8017.83,507.52 8117.83,507.52 8137.83,487.52 8137.83,20
GND on Layer 1 - Top Layer "Layer 1 - Top Layer-GND 1" (solid, remove dead copper, pour order 28): 700,20 700,675 2735,675 2865,545 2865,20
C_VCC on Layer 4 - Signal "Layer 4 - Signal-C_VCC" (solid, remove dead copper, pour order 42): 1320,695 1160,855 1160,1555 1295,1690 1295,1936.46 1348.54,1990 1710,1990 1835,2115 2925,2115 3220,2410 3220,4210 3250,4240 4045.92,4240 4090,4284.08 4090,4438.54 4151.46,4500 4470,4500 4520,4450 4520,4225 4420,4125 4420,1540 3575,695
+3.3VLMK on Layer 4 - Signal "Layer 5 - GND-+3.3VLMK" (solid, remove dead copper, pour order 24): 2385,4270 2770,4270 4025,4270 4060,4305 4060,4450 4090,4480 4145,4535 4255,4535 4495,4535 4550,4480 4550,4205 4450,4105 4450,1520 3595,665 2430,665 1295,665 1130,830 1130,1520 1095,1555 885,1555 850,1520 850,895 650,695 650,215 830,35 5325,35 7070,1780 7070,5810 6280,6600 3970,6600 3440,6070 2895,6070 2820,5995 2820,4625 2770,4575 2385,4575 2340,4530 2340,4315
P3V3_LMX on Layer 4 - Signal "Layer 4 - Signal-P3V3_LMX" (solid, remove dead copper, pour order 32): 2210,6350 2365,6505 2830,6505 3085,6760 3085,7430 4615,8960 5430,8960 5515,9045 6190,9045 6300,9155 6365,9155 6380,9140 6380,8980 6625,8735 6745,8735 6770,8710 6770,8660 6875,8555 7655,8555 8200,8010 8200,6010 8725,5485 8970,5485 9040,5415 9160,5295 9160,5125 9130,5095 9015,5095 8850,4930 8800,4930 8735,4865 8735,4755 8735,4720 8710,4695 8645,4695 8530,4580 8530,3910 9100,3340 9100,1005 8980,885 8730,885 8545,700 7915,700 7870,745 7870.5,995.5 7840,1026 7704,1026 7690,1040 7690,1084 7681,1093 7543,1093 7527,1109 7411,1109 7260,1260 7105,1415 7105,5835 6295,6645 3940,6645 3420,6125 2240,6125 2210,6155
+3.3V_LMXRF on Layer 4 - Signal "Layer 4 - Signal-+3.3V_LMXRF" (solid, remove dead copper, pour order 30): 2745,5730 2195,5730 1920,6005 1920,6370 1760,6530 1760,7250 4315,9805 9245,9805 9810,9240 9810,625 9215,30 7250,30 7175,105 7175,865 7405,1095 7515,1095 7530,1080 7620,1080 7650,1050 7650,985 7680,955 7795,955 7835,915 7835,735 7899.6,670.4 8555.4,670.4 8560,675 8740,855 8995,855 9150,1010 9150,1110 9150,3360 8565,3945 8565,4615 8645,4695 8725,4695 8750,4720 8750,4790 8755,4795 8775,4795 8800,4820 8800,4900 8815,4915 8860,4915 9030,5085 9130,5085 9175,5130 9175,5435 9090,5520 8740,5520 8250,6010 8250,8035 7715,8570 6890,8570 6785,8675 6785,8725 6760,8750 6720,8750 6705,8765 6705,8780 6675,8810 6605,8810 6410,9005 6410,9140 6375,9175 6120,9175 6020,9075 5475,9075 5400,9000 4580,9000 3035,7455 3035,6820 2745,6530 2350,6530 2190,6370 2190,6090 2335,5945 2745,5945 2765,5925 2765,5750
VDDD33 on Layer 4 - Signal "Layer 5 - GND-VDDD33" (solid, remove dead copper, pour order 4): 1570,3455 2200,4085 2745,4085 2765,4065 2765,3870 2745,3850 2345,3850 1975,3480 1975,3260 1955,3240 1590,3240 1570,3260
+3.3V_VCO on Layer 4 - Signal "Layer 5 - GND-No Net" (solid, remove dead copper, pour order 14): 2320,5180 1835,4695 1430,4695 1295,4560 1295,4030 1085,3820 730,3820 530,3620 530,2105 660,1975 660,1780 820,1620 820,920 700,800 150,800 30,920 30,5130 540,5640 1820,5640 2030,5430 2690,5430 2740,5380 2740,5230 2690,5180
+3.3V_CDCM7005 on Layer 4 - Signal "Layer 5 - GND-No Net 1" (solid, remove dead copper, pour order 12): 2745,4750 2360,4750 2295,4685 2295,4225 1395,3325 1365,3325 1205,3165 1165,3165 1135,3135 975,3135 925,3085 925,2645 775,2495 775,2180 965,1990 1210,1990 1265,1935 1265,1705 1225,1665 995,1665 840,1665 695,1810 695,1985 570,2110 570,3620 750,3800 1110,3800 1320,4010 1320,4540 1450,4670 1850,4670 2180,5000 2745,5000 2765,4980 2765,4770
VREGIN on Layer 4 - Signal "Layer 5 - GND-No Net 2" (solid, remove dead copper, pour order 8): 1525,3310 1545,3290 1545,3250 1610,3185 1990,3185 2005,3200 2005,3470 2120,3585 2805,3585 2900,3490 2900,2205 2840,2145 1820,2145 1695,2020 980,2020 800,2200 800,2480 940,2620 940,3065 985,3110 1295,3110 1370,3185 1405,3185 1470,3250 1470,3290 1490,3310
P4V5 on Layer 3 - Signal "Layer 5 - GND-P4V5" (solid, remove dead copper, pour order 26): 1130,7080 1160,7110 1345,7110 1380,7145 1380,7280 1505,7405 2025,7405 2050,7430 2050,7575 4280,9805 8075,9805 8725,9805 9630.01,8899.99 9630,6200 9540,6110 8165,6110 7350,6110 7260,6200 7260,8100 7980,8820 7980,8970 7980,9395 7915,9460 4765,9460 2685,7380 2685,7095 2685,6620 2540,6475 1275,6475 1130,6620
GND on Layer 2 - GND Layer "Layer 2 - GND Layer-GND" (solid, remove dead copper, pour order 34): 20,20 9820,20 9820,9820 20,9820
GND on Layer 5 - GND "Layer 5 - GND-GND" (solid, remove dead copper, pour order 36): 20,20 9820,20 9820,9820 20,9820

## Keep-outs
Keep-Out Layer:
  text ".Layer_Name" at -231.28,-1903.37 h60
